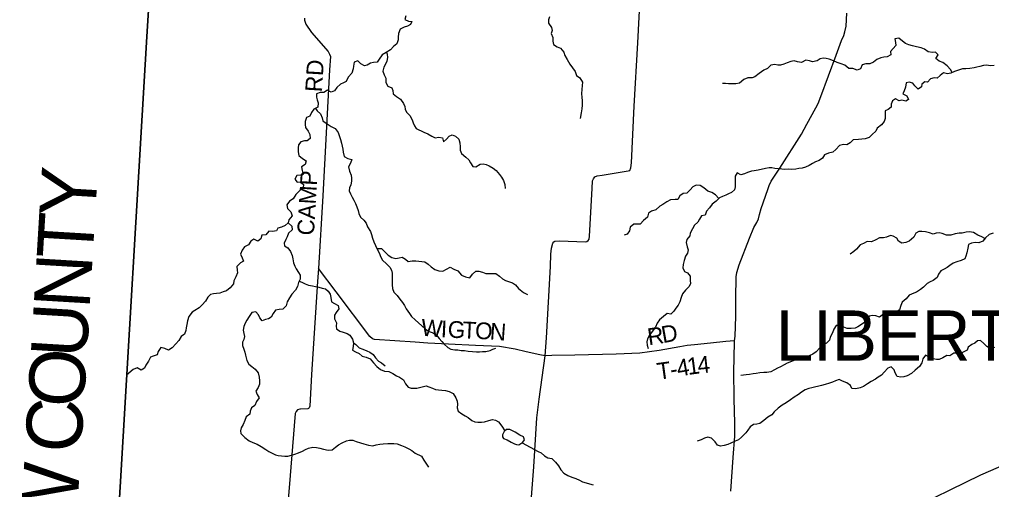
# Model space of a CAD drawing. Extents: x 1759416 to 2214760, y 252598 to 1116833.
# Drawn here: x 1926571 to 1943940, y 865784 to 874189 of the extents above; entities that cross this region are included whole.
import ezdxf

# ---------------------------------------------------------------- set-up
doc = ezdxf.new("R2010")
doc.units = 0
for name, color, linetype in [('GM_X_Adjacent_County', 7, 'Continuous'), ('GM_X_Adjacent_County_Text', 7, 'Continuous'), ('GM_X_County', 7, 'Continuous'), ('GM_X_County_Road', 7, 'Continuous'), ('GM_X_Minor_Lake', 7, 'Continuous'), ('GM_X_Minor_River', 7, 'Continuous'), ('GM_X_Township', 7, 'Continuous'), ('GM_X_Township_Road', 7, 'Continuous'), ('GM_X_Township_Road_Text', 7, 'Continuous'), ('GM_X_Township_Text', 7, 'Continuous')]:
    doc.layers.add(name, color=color, linetype=linetype)

msp = doc.modelspace()

# ---------------------------------------------------------------- linework, layer by layer
at = {"layer": 'GM_X_Adjacent_County'}
msp.add_lwpolyline([(1929994, 894165), (1929509, 885709), (1929483, 885147), (1929313, 880637), (1929312, 880613), (1928987, 876105), (1928954, 875572), (1928932, 875213), (1928849, 873883), (1928341, 865325)], dxfattribs=at)
at = {"layer": 'GM_X_County'}
msp.add_lwpolyline([(1928341, 865325), (1928849, 873883), (1928932, 875213), (1928954, 875572), (1928987, 876105), (1929312, 880613), (1929313, 880637), (1929483, 885147), (1929509, 885709), (1929994, 894165)], dxfattribs=at)
at = {"layer": 'GM_X_County_Road'}
for points in [[(1935678, 865103), (1935759, 866193), (1935817, 867067), (1935854, 867400), (1935965, 868174), (1935988, 868499), (1936058, 869773), (1936068, 869994), (1936079, 870102), (1936101, 870188), (1936120, 870214), (1936136, 870224), (1936222, 870228), (1936685, 870213), (1936711, 870219), (1936735, 870237), (1936749, 870259), (1936759, 870315), (1936805, 871164), (1936808, 871302), (1936827, 871340), (1936849, 871372), (1936893, 871392), (1936985, 871405), (1937449, 871481), (1937479, 871489), (1937497, 871537), (1937504, 871627), (1937555, 872640), (1937617, 873770), (1937692, 875153)], [(1944608, 866417), (1943740, 866043), (1942379, 865372)]]:
    msp.add_lwpolyline(points, dxfattribs=at)
at = {"layer": 'GM_X_Minor_Lake'}
for points in [[(1935564, 866630), (1935597, 866675), (1935576, 866726), (1935512, 866758), (1935426, 866813), (1935331, 866857), (1935275, 866855), (1935230, 866822), (1935201, 866760), (1935199, 866724), (1935219, 866699), (1935285, 866671), (1935356, 866632), (1935418, 866601), (1935454, 866587), (1935494, 866582)], [(1935494, 866582), (1935564, 866630)]]:
    msp.add_lwpolyline(points, dxfattribs=at)
at = {"layer": 'GM_X_Minor_River'}
for points in [[(1933475, 874252), (1933459, 874188), (1933520, 874158), (1933582, 874149), (1933560, 874096), (1933506, 874070), (1933442, 874052), (1933375, 874015), (1933345, 873939), (1933340, 873873), (1933338, 873823), (1933315, 873755), (1933253, 873707), (1933200, 873643), (1933126, 873600), (1933054, 873558), (1933001, 873481), (1932961, 873427), (1932897, 873421), (1932846, 873404), (1932784, 873374), (1932734, 873358), (1932672, 873395), (1932617, 873447), (1932550, 873424), (1932542, 873354), (1932536, 873304), (1932511, 873228), (1932446, 873154), (1932408, 873078), (1932358, 873055), (1932307, 873033), (1932239, 872973), (1932198, 872910), (1932138, 872886), (1932073, 872926), (1932008, 872881), (1931942, 872885), (1931880, 872860), (1931877, 872800), (1931893, 872749), (1931907, 872695), (1931902, 872623), (1931830, 872582), (1931787, 872524), (1931757, 872460), (1931697, 872436), (1931678, 872362), (1931678, 872308), (1931681, 872258), (1931727, 872192), (1931758, 872129), (1931764, 872061), (1931713, 872016), (1931663, 872016), (1931599, 872000), (1931555, 871945), (1931550, 871895), (1931552, 871824), (1931565, 871754), (1931631, 871702), (1931691, 871661), (1931676, 871593), (1931612, 871556), (1931625, 871489), (1931643, 871419), (1931591, 871404), (1931529, 871396), (1931490, 871332), (1931536, 871278), (1931588, 871283), (1931645, 871239), (1931639, 871187), (1931572, 871127), (1931508, 871062), (1931459, 870984), (1931397, 870938), (1931348, 870875), (1931360, 870806), (1931420, 870750), (1931445, 870676), (1931384, 870606), (1931372, 870554), (1931438, 870495), (1931445, 870427), (1931379, 870370), (1931356, 870304), (1931332, 870252), (1931303, 870190), (1931309, 870140), (1931369, 870103), (1931416, 870039), (1931444, 869971), (1931455, 869906), (1931469, 869838), (1931490, 869778), (1931516, 869728), (1931559, 869665)], [(1936043, 874238), (1936023, 874180), (1936026, 874124), (1936079, 874046), (1936087, 873990), (1936072, 873940), (1936098, 873866), (1936103, 873800), (1936112, 873742), (1936178, 873696), (1936235, 873673), (1936297, 873606), (1936316, 873544), (1936355, 873474), (1936402, 873392), (1936451, 873324), (1936501, 873259), (1936524, 873189), (1936585, 873143), (1936629, 873066), (1936624, 873010), (1936617, 872935), (1936611, 872867), (1936618, 872793), (1936625, 872741), (1936627, 872655), (1936620, 872592), (1936609, 872518), (1936588, 872415)], [(1943234, 873239), (1943206, 873294), (1943146, 873359), (1943069, 873420), (1943001, 873441), (1942944, 873488), (1942983, 873556), (1942940, 873606), (1942882, 873597), (1942808, 873608), (1942744, 873657), (1942681, 873682), (1942599, 873697), (1942529, 873716), (1942463, 873737), (1942403, 873760), (1942348, 873799), (1942282, 873854), (1942214, 873843), (1942223, 873775), (1942232, 873721), (1942179, 873667), (1942135, 873616), (1942140, 873557), (1942077, 873522), (1942015, 873513), (1941964, 873502), (1941892, 873475), (1941829, 873425), (1941764, 873398), (1941692, 873397), (1941626, 873378), (1941597, 873304), (1941538, 873281), (1941461, 873312), (1941390, 873309), (1941317, 873372), (1941253, 873393), (1941184, 873418), (1941116, 873447), (1941038, 873479), (1940982, 873491), (1940930, 873496), (1940878, 873483), (1940821, 873446), (1940741, 873431), (1940687, 873447), (1940619, 873462), (1940544, 873421), (1940472, 873430), (1940411, 873447), (1940356, 873436), (1940286, 873411), (1940231, 873388), (1940171, 873370), (1940121, 873369), (1940065, 873386), (1939997, 873371), (1939934, 873314), (1939869, 873284), (1939790, 873225), (1939713, 873164), (1939660, 873145), (1939586, 873144), (1939516, 873117), (1939437, 873050), (1939372, 873039), (1939242, 873040), (1939186, 873043), (1939134, 873042)], [(1933131, 873603), (1933142, 873568), (1933145, 873508), (1933133, 873444), (1933110, 873390), (1933082, 873334), (1933065, 873266), (1933087, 873196), (1933116, 873139), (1933120, 873061), (1933151, 872997), (1933225, 872966), (1933245, 872916), (1933250, 872860), (1933308, 872813), (1933382, 872761), (1933435, 872686), (1933455, 872632), (1933462, 872582), (1933484, 872528), (1933547, 872469), (1933589, 872393), (1933606, 872341), (1933630, 872286), (1933658, 872236)], [(1943984, 873365), (1943918, 873362), (1943848, 873369), (1943798, 873366), (1943731, 873348), (1943679, 873335), (1943629, 873322), (1943554, 873309), (1943482, 873308), (1943422, 873305), (1943346, 873282), (1943275, 873257), (1943211, 873229), (1943152, 873218), (1943082, 873235), (1943024, 873188), (1942967, 873141), (1942917, 873145), (1942850, 873124), (1942797, 873069), (1942747, 873073), (1942695, 873034), (1942688, 872984), (1942629, 872941), (1942566, 873000), (1942532, 873050), (1942467, 873065), (1942416, 873056), (1942399, 872978), (1942376, 872914), (1942355, 872860), (1942423, 872825), (1942458, 872755), (1942407, 872727)], [(1942407, 872727), (1942339, 872744), (1942289, 872731), (1942224, 872770), (1942169, 872733), (1942148, 872675), (1942147, 872618), (1942090, 872577), (1942040, 872554), (1942037, 872488), (1942036, 872419), (1942023, 872367), (1941972, 872306), (1941897, 872247), (1941872, 872189), (1941809, 872130), (1941754, 872076), (1941679, 872057), (1941619, 872050), (1941565, 872041), (1941465, 872034), (1941412, 871981), (1941355, 871948), (1941297, 871950), (1941225, 871933), (1941157, 871866), (1941101, 871815), (1941024, 871796), (1940956, 871771), (1940921, 871709), (1940862, 871664), (1940795, 871642), (1940739, 871615), (1940682, 871576), (1940617, 871545), (1940555, 871532), (1940497, 871522), (1940441, 871513), (1940366, 871508), (1940310, 871511), (1940240, 871508), (1940190, 871509), (1940126, 871515), (1940070, 871526), (1940016, 871533), (1939966, 871534), (1939900, 871523), (1939771, 871492), (1939701, 871485), (1939649, 871474), (1939578, 871451), (1939528, 871430), (1939461, 871408), (1939396, 871445), (1939359, 871388), (1939360, 871326), (1939359, 871274), (1939356, 871195), (1939349, 871145), (1939294, 871094), (1939241, 871073), (1939191, 871045), (1939134, 871022), (1939080, 870999), (1939019, 870937), (1938948, 870886), (1938899, 870819), (1938846, 870763), (1938825, 870689), (1938756, 870678), (1938719, 870618), (1938693, 870567), (1938634, 870513), (1938597, 870448), (1938553, 870370), (1938546, 870318), (1938497, 870257), (1938485, 870203), (1938501, 870122), (1938521, 870070), (1938506, 870008), (1938471, 869954), (1938449, 869880), (1938430, 869808), (1938425, 869750), (1938456, 869681), (1938508, 869657), (1938555, 869602), (1938554, 869530), (1938561, 869461), (1938532, 869408), (1938469, 869350), (1938418, 869281), (1938391, 869215), (1938372, 869143), (1938341, 869083), (1938298, 869026), (1938261, 868974), (1938212, 868921), (1938146, 868934), (1938081, 868880)], [(1931859, 872599), (1931892, 872553), (1931951, 872501), (1931981, 872432), (1931994, 872374), (1932072, 872322), (1932141, 872275), (1932213, 872240), (1932265, 872168), (1932290, 872098), (1932306, 872045), (1932325, 871977), (1932337, 871925), (1932346, 871871), (1932354, 871813), (1932373, 871740), (1932439, 871702), (1932509, 871687), (1932487, 871622), (1932450, 871556), (1932467, 871477), (1932495, 871407), (1932506, 871349), (1932504, 871295), (1932490, 871231), (1932467, 871179), (1932465, 871127), (1932486, 871069), (1932514, 871014), (1932543, 870960), (1932575, 870896), (1932597, 870840), (1932622, 870771), (1932636, 870717), (1932663, 870655), (1932727, 870598), (1932766, 870546), (1932792, 870480), (1932841, 870395), (1932861, 870343), (1932878, 870277), (1932904, 870214), (1932931, 870148), (1932971, 870072), (1933002, 870003), (1933020, 869951), (1933059, 869883), (1933131, 869820), (1933188, 869760), (1933220, 869705), (1933232, 869653), (1933233, 869575), (1933230, 869503), (1933228, 869443), (1933238, 869381), (1933261, 869315), (1933319, 869252), (1933370, 869188), (1933416, 869127), (1933451, 869073), (1933483, 869013), (1933538, 868930), (1933576, 868880), (1933639, 868817)], [(1933658, 872236), (1933796, 872176), (1933870, 872141), (1933941, 872104), (1933999, 872075), (1934063, 872086), (1934131, 872071), (1934146, 872001), (1934203, 872046), (1934250, 872103), (1934302, 872127), (1934362, 872100), (1934423, 872047), (1934440, 871984), (1934443, 871912), (1934448, 871850), (1934472, 871791), (1934545, 871724), (1934600, 871679), (1934631, 871625), (1934674, 871560), (1934726, 871555), (1934805, 871604), (1934855, 871608), (1934907, 871597), (1934965, 871574), (1935033, 871531), (1935090, 871486), (1935151, 871419), (1935184, 871366), (1935217, 871310), (1935246, 871239), (1935249, 871165)], [(1939068, 870986), (1939007, 871054), (1938943, 871093), (1938872, 871120), (1938800, 871181), (1938735, 871222), (1938659, 871223), (1938602, 871198), (1938557, 871140), (1938494, 871085), (1938432, 871076), (1938373, 871035), (1938334, 870971), (1938284, 870972), (1938206, 870961), (1938135, 870928), (1938066, 870880), (1938010, 870849), (1937941, 870784), (1937864, 870761), (1937813, 870723), (1937794, 870652), (1937723, 870592), (1937662, 870527), (1937600, 870530), (1937548, 870529), (1937483, 870477), (1937468, 870409), (1937429, 870352), (1937378, 870332)], [(1931372, 870554), (1931316, 870502), (1931253, 870475), (1931185, 870459), (1931163, 870407), (1931093, 870396), (1931027, 870402), (1930974, 870336), (1930904, 870331), (1930882, 870265), (1930829, 870227), (1930760, 870260), (1930707, 870224), (1930663, 870162), (1930592, 870121), (1930552, 870061), (1930523, 869993), (1930553, 869929), (1930574, 869865), (1930522, 869835), (1930458, 869771), (1930459, 869707), (1930467, 869657), (1930440, 869585), (1930402, 869513), (1930393, 869459), (1930335, 869392), (1930272, 869336), (1930212, 869316), (1930150, 869297), (1930092, 869287), (1930036, 869286), (1929986, 869270), (1929935, 869222), (1929893, 869154), (1929836, 869085), (1929780, 869035), (1929707, 868985), (1929655, 868956), (1929597, 868878), (1929576, 868802), (1929559, 868734), (1929549, 868678), (1929543, 868626), (1929520, 868564), (1929460, 868523), (1929417, 868447), (1929363, 868391), (1929300, 868317), (1929236, 868276), (1929166, 868306), (1929098, 868321), (1929048, 868251), (1929029, 868191), (1928963, 868166), (1928913, 868150), (1928876, 868082), (1928828, 868008), (1928805, 867954), (1928743, 867921), (1928673, 867963), (1928603, 867932), (1928484, 867831)], [(1943970, 870368), (1943895, 870343), (1943832, 870286), (1943783, 870222), (1943712, 870197), (1943648, 870200), (1943582, 870189), (1943528, 870164), (1943513, 870100), (1943495, 870018), (1943482, 869958), (1943465, 869906), (1943397, 869879), (1943322, 869858), (1943256, 869829), (1943197, 869787), (1943146, 869754), (1943092, 869723), (1943031, 869695), (1942992, 869634), (1942969, 869576), (1942896, 869523), (1942844, 869495), (1942789, 869466), (1942724, 869403), (1942671, 869359), (1942601, 869314), (1942550, 869295), (1942469, 869260), (1942412, 869191), (1942341, 869135), (1942320, 869075), (1942295, 868998), (1942244, 868962), (1942194, 868949), (1942129, 868912), (1942074, 868961), (1942007, 868917), (1941936, 868868), (1941873, 868891), (1941807, 868894), (1941756, 868883), (1941702, 868845), (1941676, 868776), (1941618, 868736), (1941551, 868695), (1941501, 868672), (1941432, 868663), (1941362, 868666), (1941298, 868689), (1941227, 868716), (1941163, 868715), (1941121, 868653), (1941098, 868587), (1941055, 868508), (1941044, 868456), (1940991, 868402), (1940937, 868369), (1940872, 868320), (1940803, 868246), (1940748, 868203), (1940683, 868174), (1940631, 868158), (1940569, 868145), (1940514, 868134), (1940434, 868101), (1940367, 868076), (1940288, 868041), (1940236, 868012), (1940171, 867980), (1940117, 867953), (1940064, 867922)], [(1943821, 870272), (1943764, 870303), (1943696, 870332), (1943617, 870381), (1943545, 870390), (1943485, 870383), (1943412, 870366), (1943360, 870369), (1943292, 870358), (1943214, 870333), (1943137, 870332), (1943058, 870363), (1943006, 870376), (1942950, 870367), (1942895, 870349), (1942831, 870372), (1942762, 870391), (1942694, 870398), (1942643, 870397), (1942587, 870368), (1942548, 870294), (1942470, 870225), (1942408, 870202), (1942338, 870189), (1942274, 870226), (1942245, 870276), (1942183, 870317), (1942131, 870326), (1942063, 870295), (1942007, 870285), (1941940, 870282), (1941872, 870249), (1941797, 870212), (1941715, 870217), (1941652, 870182), (1941590, 870157), (1941526, 870082), (1941476, 870038), (1941411, 869993)], [(1932961, 870092), (1933037, 870093), (1933089, 870047), (1933160, 869976), (1933222, 869932), (1933296, 869915), (1933356, 869929), (1933410, 869938), (1933466, 869904), (1933517, 869862), (1933589, 869875), (1933655, 869873)], [(1933655, 869873), (1933812, 869853), (1933872, 869814), (1933929, 869767), (1933992, 869716), (1934064, 869693), (1934134, 869690), (1934201, 869723), (1934264, 869762), (1934331, 869727), (1934403, 869692), (1934470, 869619), (1934539, 869586), (1934617, 869567), (1934668, 869634), (1934723, 869688), (1934776, 869691), (1934847, 869672), (1934903, 869647), (1934965, 869646), (1935021, 869649), (1935081, 869649), (1935149, 869597), (1935202, 869553), (1935254, 869522), (1935328, 869499), (1935379, 869482), (1935431, 869445), (1935488, 869378), (1935575, 869305), (1935649, 869273)], [(1931559, 869665), (1931585, 869615), (1931584, 869547), (1931556, 869485), (1931537, 869415), (1931505, 869349), (1931440, 869278), (1931398, 869212), (1931355, 869142), (1931339, 869068), (1931278, 869008), (1931214, 869005), (1931144, 868991), (1931107, 868929), (1931071, 868866), (1931019, 868838), (1930969, 868824), (1930906, 868801), (1930865, 868853), (1930845, 868909), (1930792, 868962), (1930723, 868948), (1930673, 868878), (1930634, 868813), (1930604, 868757), (1930581, 868697), (1930571, 868635), (1930579, 868577), (1930590, 868520), (1930580, 868468), (1930557, 868417), (1930555, 868362), (1930580, 868292), (1930598, 868242), (1930612, 868186), (1930631, 868094), (1930670, 868023), (1930722, 867983), (1930780, 867938), (1930839, 867870), (1930857, 867795), (1930860, 867725), (1930860, 867671), (1930839, 867607), (1930795, 867544), (1930820, 867485), (1930854, 867425), (1930809, 867359), (1930779, 867289), (1930718, 867244), (1930692, 867184), (1930685, 867134), (1930623, 867086), (1930596, 867016), (1930566, 866946), (1930533, 866888), (1930519, 866836), (1930529, 866784), (1930596, 866714), (1930674, 866657), (1930738, 866625), (1930817, 866594), (1930891, 866553), (1930973, 866501), (1931026, 866464), (1931084, 866432), (1931144, 866407), (1931196, 866395), (1931256, 866389), (1931312, 866384), (1931366, 866384), (1931434, 866401), (1931492, 866417), (1931556, 866440), (1931627, 866470), (1931679, 866498), (1931733, 866523), (1931813, 866543), (1931879, 866536), (1931939, 866524), (1932001, 866509), (1932085, 866491), (1932159, 866496), (1932217, 866540), (1932274, 866582), (1932336, 866621), (1932412, 866653), (1932466, 866668), (1932528, 866666), (1932588, 866645), (1932662, 866619), (1932722, 866602), (1932806, 866576), (1932882, 866563), (1932944, 866581), (1933012, 866594), (1933068, 866602), (1933150, 866609), (1933260, 866609), (1933320, 866600), (1933398, 866570)], [(1931568, 869512), (1931614, 869489), (1931674, 869462), (1931738, 869440), (1931807, 869425), (1931863, 869413), (1931923, 869402), (1931981, 869386), (1932037, 869371), (1932089, 869333), (1932120, 869275), (1932134, 869218), (1932145, 869140), (1932201, 869112), (1932263, 869075), (1932280, 869015), (1932232, 868951), (1932199, 868900), (1932199, 868839), (1932238, 868763), (1932228, 868705), (1932234, 868655), (1932293, 868618), (1932355, 868600), (1932425, 868577), (1932477, 868547), (1932522, 868475), (1932540, 868408), (1932531, 868344), (1932521, 868276), (1932575, 868248), (1932638, 868219), (1932696, 868171), (1932764, 868150), (1932836, 868120), (1932899, 868049), (1932957, 867987), (1933022, 867928), (1933096, 867902), (1933168, 867895), (1933240, 867861), (1933309, 867818), (1933361, 867792), (1933431, 867743), (1933468, 867677), (1933518, 867614), (1933570, 867598), (1933674, 867597)], [(1933639, 868817), (1933822, 868657), (1933889, 868612), (1933961, 868585), (1934020, 868546), (1934073, 868485), (1934117, 868432), (1934160, 868382), (1934223, 868325), (1934281, 868296), (1934351, 868283), (1934401, 868280), (1934465, 868273), (1934525, 868268), (1934587, 868261), (1934667, 868252), (1934735, 868247), (1934793, 868248), (1934843, 868250), (1934903, 868255), (1934980, 868270), (1935030, 868291), (1935085, 868312)], [(1938081, 868880), (1938008, 868817), (1937965, 868760), (1937936, 868686), (1937877, 868612), (1937828, 868547), (1937790, 868477), (1937780, 868425), (1937785, 868367), (1937806, 868304)], [(1943990, 868326), (1943923, 868299), (1943854, 868342), (1943803, 868397), (1943741, 868450), (1943691, 868442), (1943640, 868399), (1943588, 868376), (1943523, 868328), (1943502, 868277), (1943423, 868236), (1943371, 868220), (1943317, 868225), (1943265, 868222)], [(1932540, 868408), (1932580, 868380), (1932641, 868317), (1932709, 868291), (1932775, 868264), (1932831, 868240), (1932888, 868198), (1932932, 868139), (1932985, 868077), (1933039, 868048), (1933105, 867996)], [(1943265, 868222), (1943192, 868177), (1943142, 868179), (1943071, 868140), (1943005, 868107), (1942953, 868112), (1942897, 868123), (1942835, 868146), (1942761, 868189), (1942712, 868119), (1942693, 868051), (1942654, 867984), (1942577, 867918), (1942508, 867859), (1942433, 867816), (1942375, 867797), (1942318, 867792), (1942252, 867805), (1942219, 867869), (1942202, 867926), (1942145, 867977), (1942089, 867955), (1942021, 867884), (1941974, 867831), (1941914, 867791), (1941863, 867758), (1941790, 867715), (1941725, 867674), (1941649, 867627), (1941592, 867601), (1941516, 867586), (1941446, 867591), (1941422, 867646), (1941353, 867693), (1941279, 867724), (1941218, 867749), (1941151, 867726), (1941099, 867707), (1941044, 867685), (1940968, 867660), (1940903, 867643), (1940853, 867634), (1940779, 867617), (1940726, 867605), (1940674, 867592), (1940608, 867567), (1940545, 867526), (1940488, 867486), (1940411, 867433), (1940350, 867386), (1940267, 867333), (1940197, 867292), (1940128, 867241), (1940058, 867174), (1940016, 867120), (1939943, 867081), (1939868, 867016), (1939797, 866963), (1939746, 866951), (1939684, 866946), (1939625, 866903), (1939587, 866847), (1939548, 866796), (1939472, 866722), (1939416, 866675), (1939359, 866648), (1939280, 866613), (1939228, 866591), (1939163, 866570), (1939099, 866557), (1939045, 866576), (1939000, 866639), (1938933, 866702), (1938871, 866723), (1938811, 866704), (1938750, 866674), (1938682, 866647)], [(1940064, 867922), (1939995, 867886), (1939923, 867877), (1939869, 867876), (1939797, 867871), (1939731, 867860), (1939678, 867853), (1939616, 867842), (1939558, 867834), (1939508, 867831), (1939457, 867826)], [(1933674, 867597), (1933836, 867636), (1933888, 867621), (1933951, 867596), (1934003, 867575), (1934059, 867565), (1934115, 867560), (1934181, 867555), (1934251, 867540), (1934321, 867501), (1934370, 867426), (1934393, 867363), (1934396, 867309), (1934393, 867243), (1934412, 867187), (1934477, 867138), (1934533, 867105), (1934587, 867074), (1934654, 867021), (1934708, 866994), (1934762, 866989), (1934826, 866990), (1934882, 866997), (1934956, 867016), (1935025, 867034), (1935077, 867027), (1935132, 866996), (1935187, 866915), (1935246, 866833)], [(1933398, 866570), (1933456, 866545), (1933527, 866510), (1933579, 866480), (1933643, 866436)], [(1935551, 866621), (1935837, 866464), (1935895, 866440), (1935954, 866387), (1936010, 866354), (1936086, 866339), (1936151, 866274), (1936200, 866209), (1936243, 866138), (1936296, 866077), (1936366, 866034), (1936441, 866005), (1936511, 865980), (1936577, 865951), (1936633, 865924), (1936698, 865903), (1936758, 865884), (1936822, 865869)], [(1933643, 866436), (1933752, 866379), (1933795, 866311), (1933830, 866258), (1933877, 866185)]]:
    msp.add_lwpolyline(points, dxfattribs=at)
at = {"layer": 'GM_X_Township'}
msp.add_lwpolyline([(1928341, 865325), (1928849, 873883), (1928932, 875213), (1928954, 875572), (1928987, 876105), (1929312, 880613), (1929313, 880637), (1930902, 880556), (1937983, 880168), (1938742, 880137), (1938918, 880131), (1938954, 880144), (1941129, 880010), (1945394, 879799), (1950955, 879498), (1956242, 879261), (1956031, 874198), (1955719, 867780), (1955479, 863482)], dxfattribs=at)
at = {"layer": 'GM_X_Township_Road'}
for points in [[(1931663, 874213), (1931662, 874177), (1931688, 874103), (1931792, 873956), (1932086, 873615), (1932109, 873570), (1932127, 873524), (1932113, 873288), (1931989, 871037), (1931912, 869736), (1931896, 869504), (1931791, 867844), (1931758, 867275), (1931748, 867245), (1931738, 867233), (1931722, 867225), (1931594, 867222), (1931578, 867223), (1931537, 867207), (1931515, 867179), (1931499, 867141), (1931390, 865814), (1931345, 865251)], [(1939283, 865755), (1939325, 866357), (1939355, 866738), (1939351, 866969), (1939342, 867406), (1939337, 867904), (1939343, 868127), (1939349, 868442), (1939360, 868528), (1939368, 868877), (1939373, 869273), (1939375, 869513), (1939377, 869590), (1939386, 869664), (1939431, 869800), (1939616, 870281), (1939692, 870469), (1939744, 870557), (1939773, 870623), (1939793, 870703), (1939826, 870811), (1939941, 871146), (1939969, 871218), (1940004, 871296), (1940154, 871530), (1940543, 872138), (1940642, 872318), (1940798, 872608), (1940843, 872688), (1940892, 872814), (1941025, 873180), (1941165, 873549), (1941259, 873811), (1941298, 873903), (1941320, 873967), (1941339, 874066), (1941355, 874302)], [(1939349, 868442), (1939191, 868431), (1938918, 868402), (1938631, 868374), (1938503, 868362), (1938371, 868335), (1938002, 868269), (1937653, 868223), (1937230, 868207), (1936494, 868187), (1936084, 868182), (1935965, 868174), (1935871, 868193), (1935623, 868246), (1935429, 868294), (1935151, 868339), (1934718, 868362), (1934238, 868385), (1933865, 868403), (1933639, 868421), (1932915, 868469), (1932880, 868480), (1932832, 868522), (1932229, 869320), (1931912, 869736)]]:
    msp.add_lwpolyline(points, dxfattribs=at)

# ---------------------------------------------------------------- texts
at = {"layer": 'GM_X_Adjacent_County_Text'}
for s, rotation, p in [('Y', 86.5535, (1927921, 870631)), ('T', 86.5523, (1927876, 869884)), ('N', 86.552, (1927823, 869002)), ('U', 86.5535, (1927770, 868119)), ('O', 86.5524, (1927717, 867236)), ('C', 86.5456, (1927668, 866423)), ('W', 85.9958, (1927568, 864960))]:
    msp.add_text(s, height=1000, rotation=rotation, dxfattribs=at).set_placement(p)
at = {"layer": 'GM_X_Township_Road_Text'}
for s, rotation, p in [('RD', 86.5466, (1931976, 872883)), ('CAMP', 86.6189, (1931831, 870321)), ('W', 355.6021, (1933739, 868535)), ('I', 357.2704, (1934095, 868508)), ('G', 357.2487, (1934218, 868502)), ('T', 357.2538, (1934482, 868490)), ('O', 357.2267, (1934706, 868479)), ('N', 355.8838, (1934968, 868466)), ('R', 8.3189, (1937814, 868364)), ('D', 10.201, (1938068, 868401)), ('4', 9.9004, (1938340, 867801)), ('1', 7.5781, (1938519, 867833)), ('4', 6.0322, (1938700, 867857)), ('T', 8.0319, (1937984, 867746)), ('-', 10.4463, (1938220, 867779))]:
    msp.add_text(s, height=300, rotation=rotation, dxfattribs=at).set_placement(p)
at = {"layer": 'GM_X_Township_Text'}
msp.add_text('LIBERTY', height=900, rotation=0, dxfattribs=at).set_placement((1940084, 868086))

doc.saveas('drawing.dxf')
